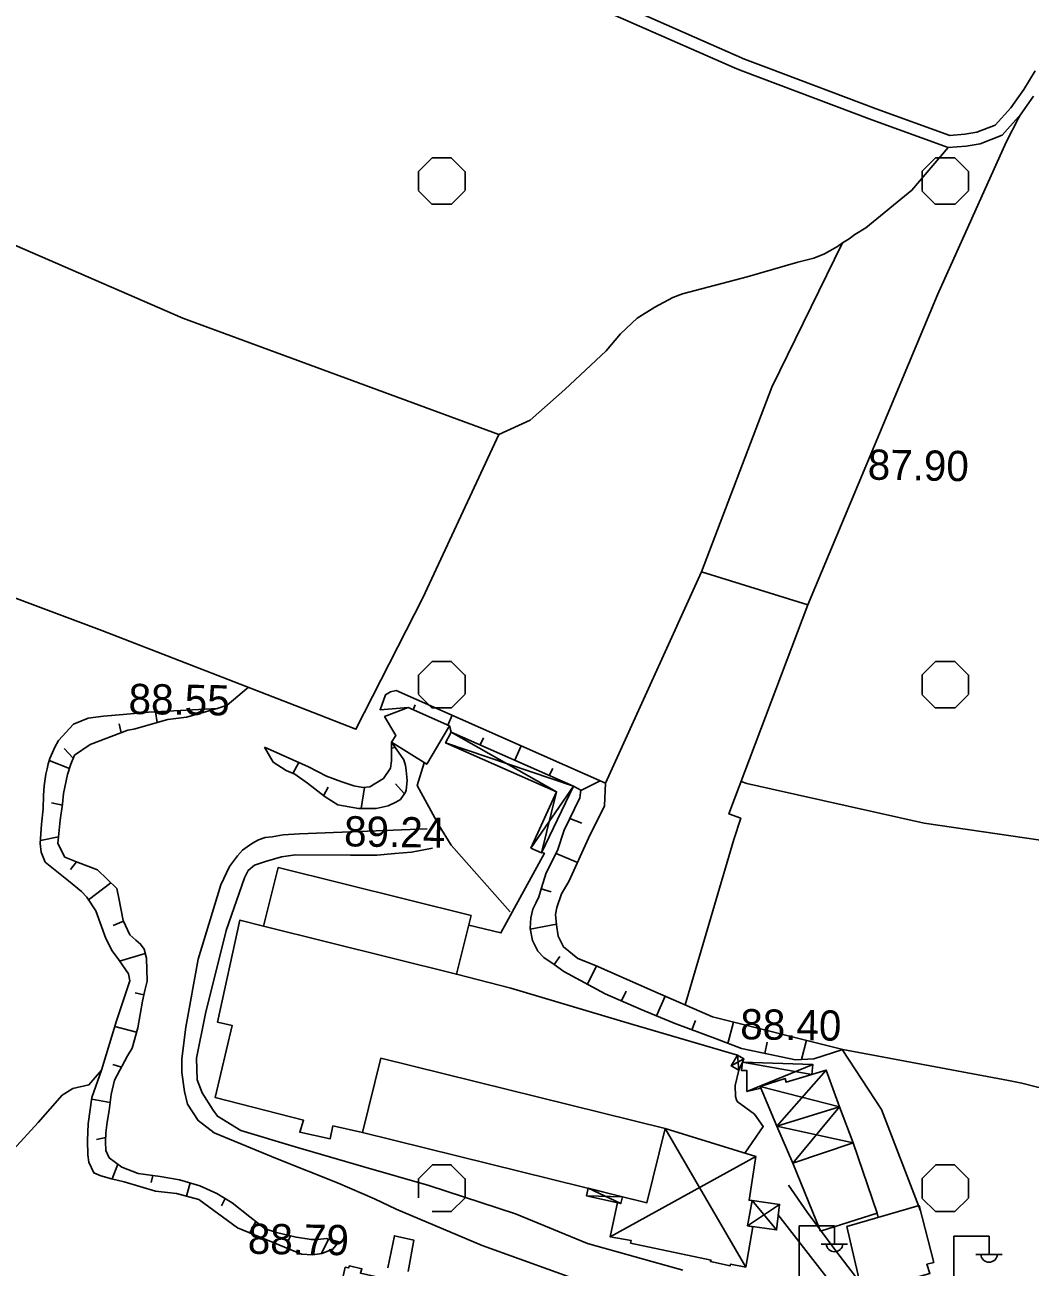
# Model space of a CAD drawing. Extents: x 417995 to 421451, y 4454518 to 4458015.
# Drawn here: x 419526.8 to 419726.5, y 4456275.9 to 4456522.5 of the extents above; entities that cross this region are included whole.
import ezdxf

# ---------------------------------------------------------------- set-up
doc = ezdxf.new("R2010")
doc.units = 0
for name, color, linetype in [('B_Betonzemin', 7, 'Continuous'), ('B_Harabe', 7, 'Continuous'), ('B_Imalat', 7, 'Continuous'), ('B_Ins_Halinde', 7, 'Continuous'), ('B_Kapi', 7, 'Continuous'), ('B_Mesken', 7, 'Continuous'), ('B_Sundurma', 7, 'Continuous'), ('S_Elektrik_Diregi', 7, 'Continuous'), ('Sev_Sevalti', 7, 'Continuous'), ('Sev_Sevustu', 7, 'Continuous'), ('Sev_Tarama', 7, 'Continuous'), ('Sinir_Duvar_tek_tarafa_ait', 7, 'Continuous'), ('Sinir_itirazli_Mulkiyet', 7, 'Continuous'), ('Sinir_Tel_bir_taraf', 7, 'Continuous'), ('TR_TARIMALANI', 7, 'Continuous'), ('Y_Kot_Noktasi', 7, 'Continuous'), ('Y_Yol_Kotu', 7, 'Continuous'), ('Yol_Sose', 7, 'Continuous'), ('Yol_Toprak_Duz', 7, 'Continuous'), ('Yol_Toprak_Kesik', 7, 'Continuous')]:
    doc.layers.add(name, color=color, linetype=linetype)

msp = doc.modelspace()

# ---------------------------------------------------------------- linework, layer by layer
at = {"layer": 'B_Betonzemin'}
for points in [[(419593.9, 4456302.57), (419588.03, 4456303.88), (419587.51, 4456301.33), (419581.43, 4456302.64), (419582.2, 4456305.03), (419564.65, 4456309.52), (419568.04, 4456323.81), (419565.08, 4456324.51), (419569.56, 4456344.77), (419574.21, 4456343.58)], [(419612.57, 4456334.02), (419623.35, 4456331.25), (419647.57, 4456324.03), (419668.38, 4456317.96)], [(419668.65, 4456314.99), (419667.9, 4456311.93), (419668, 4456309.74), (419668.2, 4456309.06), (419668.33, 4456308.77), (419671.75, 4456306.26), (419673.49, 4456303.75), (419669.82, 4456298.48)], [(419598.96, 4456275.74), (419600.25, 4456282.09), (419604.13, 4456281.19), (419603, 4456275)]]:
    msp.add_lwpolyline(points, dxfattribs=at)
at = {"layer": 'B_Harabe'}
msp.add_lwpolyline([(419611.18, 4456383.33), (419606.65, 4456375.69), (419599.65, 4456380.12), (419600.51, 4456381.4), (419598.28, 4456385.16), (419603, 4456386.97)], close=True, dxfattribs=at)
at = {"layer": 'B_Imalat'}
for points in [[(419577.12, 4456355.21), (419615.47, 4456345.65), (419612.57, 4456334.02), (419574.21, 4456343.58)], [(419654.05, 4456303.39), (419597.54, 4456317.34), (419593.9, 4456302.57), (419650.41, 4456288.63)]]:
    msp.add_lwpolyline(points, close=True, dxfattribs=at)
at = {"layer": 'B_Ins_Halinde'}
msp.add_lwpolyline([(419684.85, 4456282.98), (419679.37, 4456296.52), (419691.34, 4456300.56), (419696.13, 4456286.59)], close=True, dxfattribs=at)
at = {"layer": 'B_Kapi'}
msp.add_lwpolyline([(419609.03, 4456363.59), (419611.53, 4456359.64)], dxfattribs=at)
at = {"layer": 'B_Mesken'}
msp.add_lwpolyline([(419690.11, 4456283.93), (419693.16, 4456270.84), (419706.6, 4456274.58), (419706.01, 4456276.42), (419707.36, 4456276.8), (419704.5, 4456288.06)], close=True, dxfattribs=at)
at = {"layer": 'B_Sundurma'}
for p, q in [((419611.53, 4456382.06), (419632.45, 4456370.26)), ((419610.42, 4456379.94), (419635.84, 4456371.36)), ((419627.35, 4456359.04), (419635.84, 4456371.36)), ((419629.47, 4456358.09), (419632.45, 4456370.26)), ((419667.15, 4456315.8), (419669.66, 4456317.21)), ((419668.65, 4456314.99), (419668.38, 4456317.96)), ((419669.35, 4456316.57), (419683.17, 4456314.13)), ((419670.26, 4456310.76), (419683.38, 4456316.07)), ((419676.23, 4456303.86), (419686.01, 4456314.99)), ((419672.9, 4456311.73), (419688.68, 4456307.7)), ((419679.37, 4456296.52), (419688.68, 4456307.7)), ((419670.02, 4456275.86), (419654.05, 4456303.39)), ((419676.23, 4456303.86), (419691.34, 4456300.56)), ((419643.07, 4456281.9), (419672.03, 4456297.8)), ((419638.37, 4456290.03), (419645.52, 4456289.83)), ((419638.74, 4456291.51), (419645.24, 4456288.52)), ((419670.38, 4456284.03), (419676.76, 4456288.32)), ((419671.27, 4456289.11), (419676.14, 4456283.23))]:
    msp.add_line(p, q, dxfattribs=at)
for points in [[(419627.35, 4456359.04), (419632.45, 4456370.26), (419610.42, 4456379.94), (419611.53, 4456382.06), (419635.84, 4456371.36), (419629.47, 4456358.09)], [(419669.35, 4456316.57), (419668.65, 4456314.99), (419667.15, 4456315.8), (419668.38, 4456317.96), (419669.66, 4456317.21)], [(419672.9, 4456311.73), (419673.05, 4456311.39), (419670.26, 4456310.76), (419670.24, 4456314.91), (419669.16, 4456314.93), (419669.35, 4456316.57), (419683.38, 4456316.07), (419683.17, 4456314.13), (419678.04, 4456312.56), (419677.86, 4456313.29), (419672.9, 4456311.73)], [(419672.9, 4456311.73), (419676.23, 4456303.86), (419688.68, 4456307.7), (419686.01, 4456314.99), (419678.04, 4456312.56), (419677.86, 4456313.29)], [(419676.23, 4456303.86), (419679.37, 4456296.52), (419691.34, 4456300.56), (419688.68, 4456307.7)], [(419644.55, 4456288.67), (419643.07, 4456281.9), (419647.24, 4456281.16), (419647.15, 4456280.62), (419663.14, 4456277.26), (419663, 4456276.97), (419666.95, 4456276.12), (419666.98, 4456276.42), (419670.02, 4456275.86), (419671.44, 4456283.88), (419670.38, 4456284.03), (419671.27, 4456289.11), (419670.68, 4456289.12), (419672.03, 4456297.8), (419654.05, 4456303.39), (419650.41, 4456288.63), (419645.52, 4456289.83), (419645.24, 4456288.52)], [(419638.74, 4456291.51), (419638.37, 4456290.03), (419645.24, 4456288.52), (419645.52, 4456289.83)], [(419671.27, 4456289.11), (419670.38, 4456284.03), (419676.14, 4456283.23), (419676.76, 4456288.32)], [(419604.51, 4456263.13), (419596.9, 4456264.63), (419597.4, 4456267.56), (419589.08, 4456269.64), (419590.47, 4456275.84), (419591.14, 4456275.7), (419591.31, 4456276.1), (419593.78, 4456275.52), (419593.5, 4456274.63), (419608.95, 4456271.17), (419608.78, 4456270.74), (419619.25, 4456267.74), (419619.31, 4456267.96), (419625.9, 4456266.66), (419624.97, 4456262.16), (419604.86, 4456265.15)]]:
    msp.add_lwpolyline(points, close=True, dxfattribs=at)
at = {"layer": 'S_Elektrik_Diregi'}
for p, q in [((419680.66, 4456266.57), (419680.66, 4456284.07)), ((419680.66, 4456284.07), (419687.66, 4456284.07)), ((419687.66, 4456280.57), (419687.66, 4456284.07)), ((419685, 4456280.43), (419690.25, 4456280.43)), ((419711.36, 4456264.48), (419711.36, 4456281.98)), ((419711.36, 4456281.98), (419718.36, 4456281.98)), ((419718.36, 4456278.48), (419718.36, 4456281.98)), ((419715.7, 4456278.34), (419720.95, 4456278.34))]:
    msp.add_line(p, q, dxfattribs=at)
for centre in [(419687.66, 4456280.58), (419718.36, 4456278.49)]:
    msp.add_arc(centre, 1.66, 184.8384, 355.1464, dxfattribs=at)
at = {"layer": 'Sev_Sevalti'}
for points in [[(419689.32, 4456319.09), (419663.39, 4456325.57), (419651.6, 4456330.7), (419640.21, 4456335.73), (419636.64, 4456337.13), (419633.84, 4456339.45), (419632.79, 4456341.57), (419632.45, 4456343.82), (419632.27, 4456345.88), (419632.51, 4456347.23), (419633.42, 4456349.97), (419634.91, 4456352.4), (419638.81, 4456361.04), (419641.95, 4456367.44), (419642.14, 4456371.95), (419600.56, 4456390.34), (419599.45, 4456390.06), (419598.44, 4456389.51), (419597.38, 4456386.54)], [(419536.47, 4456383.65), (419539.41, 4456384.88), (419542.47, 4456385.26), (419546.37, 4456385.57), (419551.4, 4456386.03), (419565.17, 4456386.8)], [(419530.45, 4456366.83), (419530.54, 4456369.53), (419530.68, 4456371.42), (419530.87, 4456372.82), (419530.99, 4456373.73), (419531.28, 4456374.81), (419531.46, 4456375.78), (419531.8, 4456376.86), (419532.3, 4456378.04), (419532.81, 4456379.11), (419533.53, 4456380.45), (419536.47, 4456383.65)], [(419574.42, 4456379.07), (419583.19, 4456375.18), (419586.76, 4456373.34), (419589.82, 4456372.23), (419592.19, 4456371.41), (419593.94, 4456371.09), (419595.35, 4456371.22), (419598.08, 4456372.88), (419599.49, 4456374.91), (419599.67, 4456376.37), (419599.65, 4456380.12)], [(419589.19, 4456280.87), (419588.03, 4456279.41), (419585.8, 4456278.55), (419583.96, 4456278.31), (419581.77, 4456278.43), (419569.1, 4456283.66), (419561.41, 4456289.26), (419556.95, 4456290.5), (419552.8, 4456290.97), (419546.56, 4456292.8), (419544.03, 4456293.41), (419541.93, 4456294.01), (419540.51, 4456294.57), (419539.51, 4456296.7), (419539.32, 4456298.13), (419539.26, 4456301.02), (419539.42, 4456304.31), (419540.15, 4456309.51), (419542.09, 4456314.96), (419545.06, 4456324.76), (419547.7, 4456332.71), (419547.45, 4456334.12), (419545.47, 4456336.85), (419544.2, 4456338.65), (419542.94, 4456341.1), (419540.93, 4456346.62), (419539.13, 4456349.32), (419538.07, 4456350.45), (419535.48, 4456352.59), (419530.87, 4456356.29), (419530.04, 4456358.22), (419529.87, 4456359.95), (419530.13, 4456363.83), (419530.45, 4456366.83)]]:
    msp.add_lwpolyline(points, dxfattribs=at)
at = {"layer": 'Sev_Sevustu'}
for points in [[(419689.32, 4456319.09), (419663.39, 4456325.57), (419651.6, 4456330.7), (419640.21, 4456335.73), (419636.64, 4456337.13), (419633.84, 4456339.45), (419632.79, 4456341.57), (419632.45, 4456343.82), (419632.27, 4456345.88), (419632.51, 4456347.23), (419633.42, 4456349.97), (419634.91, 4456352.4), (419638.81, 4456361.04), (419641.95, 4456367.44), (419642.14, 4456371.95), (419600.56, 4456390.34), (419599.45, 4456390.06), (419598.44, 4456389.51), (419597.38, 4456386.54), (419603, 4456386.97), (419611.18, 4456383.33), (419611.53, 4456382.06), (419635.84, 4456371.36), (419637.28, 4456370.53), (419637.07, 4456369.07), (419633.96, 4456362.59), (419632.66, 4456358.56), (419630.37, 4456354.16), (419629.48, 4456351.15), (419628.94, 4456349.41), (419628.32, 4456348.15), (419627.76, 4456346.94), (419627.33, 4456345.22), (419627.19, 4456343.09), (419627.66, 4456340.73), (419628.71, 4456338.58), (419629.91, 4456337.34), (419631.94, 4456335.96), (419633.89, 4456334.58), (419642.11, 4456330.1), (419649.28, 4456327.03), (419655.83, 4456324.28), (419664.38, 4456321.09), (419669.21, 4456319.26), (419679.93, 4456317), (419683.56, 4456317.19), (419689.32, 4456319.09)], [(419565.06, 4456386.76), (419558.93, 4456385.08), (419555.24, 4456384.6), (419548.51, 4456382.65), (419547.31, 4456382.46), (419539.81, 4456379.66), (419536.69, 4456377.5), (419535.96, 4456375.73), (419535.33, 4456373.68), (419534.51, 4456369.92), (419534.32, 4456367.81), (419533.88, 4456364.58), (419533.38, 4456359.99), (419534.79, 4456357.27), (419537.43, 4456356.2), (419541.24, 4456354.73), (419545.07, 4456351.05), (419545.53, 4456349.1), (419546.38, 4456344.65), (419547.68, 4456341.82), (419548.85, 4456340.77), (419549.81, 4456340), (419550.5, 4456338.96), (419551.01, 4456337.17), (419551.1, 4456332.63), (419550.64, 4456330.8), (419550.17, 4456328.65), (419549.28, 4456323.37), (419548.18, 4456319.34), (419547.24, 4456317.78), (419544.67, 4456312.96), (419543.98, 4456310.16), (419543.6, 4456306.93), (419543.19, 4456304.67), (419542.94, 4456302.51), (419542.85, 4456300.73), (419542.93, 4456299), (419543.61, 4456297.58), (419546.07, 4456295.7), (419549.35, 4456294.46), (419553.72, 4456293.85), (419557.55, 4456293.19), (419561.58, 4456291.99), (419564.96, 4456290.48), (419568.01, 4456288.59), (419571.54, 4456285.83), (419574.58, 4456283.46), (419576.84, 4456282.72), (419580.72, 4456281.79), (419582.93, 4456281.49), (419583.68, 4456281.37), (419585.06, 4456281.34), (419586.66, 4456281.53), (419589.19, 4456280.87)], [(419599.65, 4456380.12), (419602.11, 4456376.6), (419602.47, 4456375.48), (419602.56, 4456374.48), (419602.8, 4456372.48), (419602.58, 4456370.59), (419602.41, 4456370.16), (419601.42, 4456368.7), (419600.49, 4456368.17), (419598.99, 4456367.46), (419596.6, 4456366.94), (419593.12, 4456366.94), (419588.99, 4456367.68), (419586.5, 4456369.21), (419582.98, 4456371.97), (419580.49, 4456373.71), (419578.72, 4456374.49), (419576.18, 4456376.13), (419574.42, 4456379.07)]]:
    msp.add_lwpolyline(points, dxfattribs=at)
at = {"layer": 'Sev_Tarama'}
for p, q in [((419553.14, 4456383.99), (419552.76, 4456386.11)), ((419560.49, 4456385.51), (419560.4, 4456386.02)), ((419603.97, 4456386.54), (419604.39, 4456387.5)), ((419545.98, 4456381.96), (419545.54, 4456383.71)), ((419610.83, 4456383.49), (419611.68, 4456385.42)), ((419617.28, 4456379.53), (419617.91, 4456380.96)), ((419536.44, 4456376.89), (419534.63, 4456378.8)), ((419600.42, 4456379.03), (419599.66, 4456378.87)), ((419624.13, 4456376.51), (419625.44, 4456379.34)), ((419535.68, 4456374.83), (419531.66, 4456376.42)), ((419580.06, 4456373.9), (419581.28, 4456376.03)), ((419630.96, 4456373.5), (419631.72, 4456374.87)), ((419586.18, 4456369.46), (419587.11, 4456371.17)), ((419593.66, 4456366.94), (419594.3, 4456371.12)), ((419602.21, 4456369.87), (419600.45, 4456371.82)), ((419637.28, 4456370.49), (419641.13, 4456372.4)), ((419534.28, 4456367.55), (419532.14, 4456368.07)), ((419635.09, 4456364.95), (419637.45, 4456364.01)), ((419533.52, 4456361.31), (419529.91, 4456360.54)), ((419537.11, 4456356.32), (419535.9, 4456354.78)), ((419632.36, 4456357.99), (419636.63, 4456356.2)), ((419543.88, 4456352.19), (419539.48, 4456348.79)), ((419629.41, 4456350.94), (419631.38, 4456350.35)), ((419546.42, 4456344.56), (419544.37, 4456343.69)), ((419627.22, 4456342.94), (419632.44, 4456343.98)), ((419550.74, 4456338.14), (419545.65, 4456336.6)), ((419631.94, 4456335.96), (419633.11, 4456337.52)), ((419638.58, 4456332.02), (419640.39, 4456335.65)), ((419550.45, 4456329.94), (419548.74, 4456330.3)), ((419645.35, 4456328.71), (419646.27, 4456330.68)), ((419652.29, 4456325.77), (419653.99, 4456329.66)), ((419659.33, 4456322.98), (419660.03, 4456324.85)), ((419666.5, 4456320.29), (419667.58, 4456324.52)), ((419549.04, 4456322.5), (419544.72, 4456323.65)), ((419673.79, 4456318.29), (419674.29, 4456320.51)), ((419681.07, 4456317.06), (419682.08, 4456320.9)), ((419546.04, 4456315.53), (419544.32, 4456316.08)), ((419543.79, 4456308.57), (419540.11, 4456309.2)), ((419542.89, 4456301.61), (419541.08, 4456301.2)), ((419545.27, 4456296.31), (419544.2, 4456293.37)), ((419552.28, 4456294.05), (419551.95, 4456292.68)), ((419559.67, 4456292.56), (419558.91, 4456289.96)), ((419566.63, 4456289.45), (419565.88, 4456288)), ((419572.7, 4456284.93), (419571.52, 4456282.66)), ((419579.62, 4456282.05), (419579.09, 4456280.91)), ((419587.15, 4456281.4), (419585.74, 4456278.54))]:
    msp.add_line(p, q, dxfattribs=at)
at = {"layer": 'Sinir_Duvar_tek_tarafa_ait'}
msp.add_lwpolyline([(419629.52, 4456358.21), (419630.03, 4456358.04), (419621.41, 4456342.23), (419614.99, 4456343.73)], dxfattribs=at)
at = {"layer": 'Sinir_itirazli_Mulkiyet'}
for points in [[(419321.24, 4456347.68), (419366.18, 4456330.2), (419404.71, 4456316.99), (419435.75, 4456305.79), (419462.17, 4456295.91), (419480.05, 4456338.51), (419511.32, 4456413.78), (419542.11, 4456402.26), (419582.61, 4456386.59), (419592.6, 4456382.64), (419605.89, 4456408.74), (419621.01, 4456441.18), (419558.2, 4456464.29), (419515.63, 4456482.76), (419481.23, 4456498.71), (419447.26, 4456516.37)], [(419724.23, 4456503.98), (419724.55, 4456504.59)], [(419689.24, 4456479.26), (419675.2, 4456450.57), (419661.24, 4456413.88), (419682.34, 4456407.38), (419708.12, 4456468.91), (419721.78, 4456499.24), (419724.23, 4456503.98)], [(419693.89, 4456482.21), (419703.04, 4456489.69), (419710.25, 4456498.17)], [(419621.01, 4456441.18), (419627.23, 4456444.05), (419634.09, 4456450.1), (419642.27, 4456457.81), (419645.14, 4456461.17), (419648.43, 4456464.25), (419651.98, 4456466.46), (419655.53, 4456468.4), (419657.49, 4456469.13), (419670.31, 4456472.49), (419680.36, 4456475.41), (419683.57, 4456476.22), (419685.64, 4456477.05), (419688.26, 4456478.52), (419689.24, 4456479.26), (419690.55, 4456480.05), (419691.7, 4456480.9), (419693.89, 4456482.21)], [(419661.24, 4456413.88), (419642.14, 4456371.95)], [(419682.34, 4456407.38), (419666.68, 4456365.85), (419669.05, 4456365), (419667.63, 4456360.75)], [(419565.06, 4456386.76), (419567.03, 4456387.42), (419571.25, 4456390.99)], [(419670.21, 4456371.89), (419669.12, 4456372.31)], [(419670.21, 4456371.89), (419705.46, 4456364.03), (419722.71, 4456361.48)], [(419722.71, 4456361.48), (419728.13, 4456360.69), (419742.37, 4456358.67)], [(419667.63, 4456360.75), (419658.01, 4456327.91)], [(419689.17, 4456319.04), (419696.98, 4456307.14), (419704.76, 4456287.05)], [(419689.32, 4456319.09), (419722.2, 4456312.91)], [(419504.94, 4456280.43), (419510.65, 4456292.59), (419513.61, 4456295.25), (419519.08, 4456296.29), (419524.53, 4456299.12), (419529.48, 4456304.6), (419534.22, 4456309.97), (419536.35, 4456311.34), (419539.55, 4456312.05), (419542.09, 4456314.96)], [(419722.2, 4456312.91), (419724.84, 4456312.41), (419727.96, 4456311.6), (419728.29, 4456311.54), (419729.64, 4456311.57), (419729.97, 4456311.68), (419730.84, 4456311.99), (419730.84, 4456311.99)], [(419696.13, 4456286.59), (419696.34, 4456285.72)]]:
    msp.add_lwpolyline(points, dxfattribs=at)
at = {"layer": 'Sinir_Tel_bir_taraf'}
for points in [[(419609.03, 4456363.59), (419604.76, 4456371.46), (419606.16, 4456376.01)], [(419623.23, 4456346.42), (419611.53, 4456359.64)]]:
    msp.add_lwpolyline(points, dxfattribs=at)
at = {"layer": 'TR_TARIMALANI'}
for p, q in [((419605, 4456493.41), (419607.71, 4456496.12)), ((419607.75, 4456496.14), (419611.58, 4456496.14)), ((419614.25, 4456493.41), (419611.54, 4456496.12)), ((419705, 4456493.41), (419707.71, 4456496.12)), ((419707.75, 4456496.14), (419711.58, 4456496.14)), ((419714.25, 4456493.41), (419711.54, 4456496.12)), ((419605.04, 4456489.6), (419605.04, 4456493.43)), ((419614.29, 4456489.6), (419614.29, 4456493.43)), ((419705.04, 4456489.6), (419705.04, 4456493.43)), ((419714.29, 4456489.6), (419714.29, 4456493.43)), ((419607.71, 4456486.87), (419605, 4456489.58)), ((419611.54, 4456486.87), (419614.25, 4456489.58)), ((419707.71, 4456486.87), (419705, 4456489.58)), ((419711.54, 4456486.87), (419714.25, 4456489.58)), ((419607.75, 4456486.89), (419611.58, 4456486.89)), ((419707.75, 4456486.89), (419711.58, 4456486.89)), ((419605, 4456393.41), (419607.71, 4456396.12)), ((419607.75, 4456396.14), (419611.58, 4456396.14)), ((419614.25, 4456393.41), (419611.54, 4456396.12)), ((419705, 4456393.41), (419707.71, 4456396.12)), ((419707.75, 4456396.14), (419711.58, 4456396.14)), ((419714.25, 4456393.41), (419711.54, 4456396.12)), ((419605.04, 4456389.6), (419605.04, 4456393.43)), ((419614.29, 4456389.6), (419614.29, 4456393.43)), ((419705.04, 4456389.6), (419705.04, 4456393.43)), ((419714.29, 4456389.6), (419714.29, 4456393.43)), ((419607.71, 4456386.87), (419605, 4456389.58)), ((419611.54, 4456386.87), (419614.25, 4456389.58)), ((419707.71, 4456386.87), (419705, 4456389.58)), ((419711.54, 4456386.87), (419714.25, 4456389.58)), ((419607.75, 4456386.89), (419611.58, 4456386.89)), ((419707.75, 4456386.89), (419711.58, 4456386.89)), ((419605, 4456293.41), (419607.71, 4456296.12)), ((419607.75, 4456296.14), (419611.58, 4456296.14)), ((419614.25, 4456293.41), (419611.54, 4456296.12)), ((419705, 4456293.41), (419707.71, 4456296.12)), ((419707.75, 4456296.14), (419711.58, 4456296.14)), ((419714.25, 4456293.41), (419711.54, 4456296.12)), ((419605.04, 4456289.6), (419605.04, 4456293.43)), ((419614.29, 4456289.6), (419614.29, 4456293.43)), ((419705.04, 4456289.6), (419705.04, 4456293.43)), ((419714.29, 4456289.6), (419714.29, 4456293.43)), ((419611.54, 4456286.87), (419614.25, 4456289.58)), ((419707.71, 4456286.87), (419705, 4456289.58)), ((419711.54, 4456286.87), (419714.25, 4456289.58)), ((419607.75, 4456286.89), (419611.58, 4456286.89)), ((419707.75, 4456286.89), (419711.58, 4456286.89))]:
    msp.add_line(p, q, dxfattribs=at)
at = {"layer": 'Yol_Sose'}
for points in [[(419639.71, 4456272.23), (419617.7, 4456280.15), (419600.57, 4456287.35), (419596.26, 4456289.42), (419588.93, 4456292.62), (419576.95, 4456297.38), (419564.41, 4456302.52), (419561.23, 4456304.95), (419559.12, 4456308.2), (419558.54, 4456310.7), (419558.01, 4456314.51), (419558, 4456317.24), (419558.78, 4456323.52), (419561.29, 4456337.01), (419565.78, 4456351.76), (419567.48, 4456355.43), (419569.06, 4456357.54), (419570.08, 4456358.63), (419570.98, 4456359.29), (419572.02, 4456360.01), (419573.25, 4456360.69), (419574.58, 4456361.13), (419575.99, 4456361.32), (419578.15, 4456361.66), (419581.4, 4456361.9), (419606.72, 4456362.87)], [(419591.55, 4456357.66), (419596.72, 4456357.68), (419600.32, 4456357.98), (419603.62, 4456358.25), (419607.83, 4456359.07)], [(419657.54, 4456275.24), (419638.6, 4456280.55), (419624.28, 4456286.43), (419607.07, 4456292.06), (419594.15, 4456295.78), (419580.53, 4456299.71), (419569.71, 4456302.99), (419565.08, 4456305.82), (419564.21, 4456307.03), (419562.02, 4456310.47), (419561.09, 4456313.07), (419560.94, 4456317.32), (419562.71, 4456326.2), (419566.84, 4456342.72), (419570.45, 4456353.17), (419571.2, 4456354.62), (419572.46, 4456355.65), (419574.66, 4456356.42), (419577.81, 4456357.32), (419580.6, 4456357.7), (419591.55, 4456357.66)], [(419721.62, 4456258.79), (419703.9, 4456262.87), (419698.27, 4456265.9), (419696.89, 4456267.19), (419695.64, 4456268.51), (419694.77, 4456269.8), (419693.35, 4456272.03), (419687.92, 4456279.12), (419682.23, 4456286.8), (419678.53, 4456292.16)], [(419676.41, 4456286.33), (419686.6, 4456273.2)]]:
    msp.add_lwpolyline(points, dxfattribs=at)
at = {"layer": 'Yol_Toprak_Duz'}
for points in [[(419491.37, 4456594.3), (419492.29, 4456594.56), (419492.72, 4456594.6), (419493.36, 4456594.59), (419494.24, 4456594.51), (419512.52, 4456587.29), (419538.36, 4456575.91), (419554.76, 4456567.87), (419582.03, 4456554.02), (419605.89, 4456542.25), (419626.25, 4456532.22), (419667.82, 4456514.01)], [(419667.82, 4456514.01), (419668.94, 4456513.52)], [(419724.23, 4456504.24), (419720.94, 4456500.61), (419716.57, 4456498.92), (419713.82, 4456498.44), (419710.25, 4456498.17), (419695.1, 4456503.64), (419668.94, 4456513.52)], [(419727.2, 4456508.34), (419724.55, 4456504.59), (419724.23, 4456504.24)]]:
    msp.add_lwpolyline(points, dxfattribs=at)
at = {"layer": 'Yol_Toprak_Kesik'}
for points in [[(419495.62, 4456596.59), (419513.46, 4456589.55), (419539.3, 4456578.16), (419555.7, 4456570.13), (419582.87, 4456556.12), (419606.73, 4456544.35), (419627.18, 4456534.48), (419669.78, 4456515.73)], [(419674.52, 4456513.94), (419669.78, 4456515.73)], [(419724.28, 4456508.3), (419722.7, 4456506.07), (419719.56, 4456502.61), (419715.94, 4456501.21), (419713.52, 4456500.79), (419710.57, 4456500.57), (419695.91, 4456505.86), (419674.52, 4456513.94)], [(419725.27, 4456509.71), (419727.5, 4456513.38)], [(419725.27, 4456509.71), (419724.28, 4456508.3)]]:
    msp.add_lwpolyline(points, dxfattribs=at)

# ---------------------------------------------------------------- texts
at = {"layer": 'Y_Kot_Noktasi'}
for s, p in [('87.90', (419694.22, 4456432.22)), ('88.55', (419547.4, 4456385.7)), ('88.40', (419668.9, 4456321.12)), ('88.79', (419571.08, 4456278.52))]:
    msp.add_text(s, height=6, rotation=359.0723, dxfattribs=at).set_placement(p)
at = {"layer": 'Y_Yol_Kotu'}
msp.add_text('89.24', height=6, rotation=359.0723, dxfattribs=at).set_placement((419590.21, 4456359.42))

doc.saveas('drawing.dxf')
